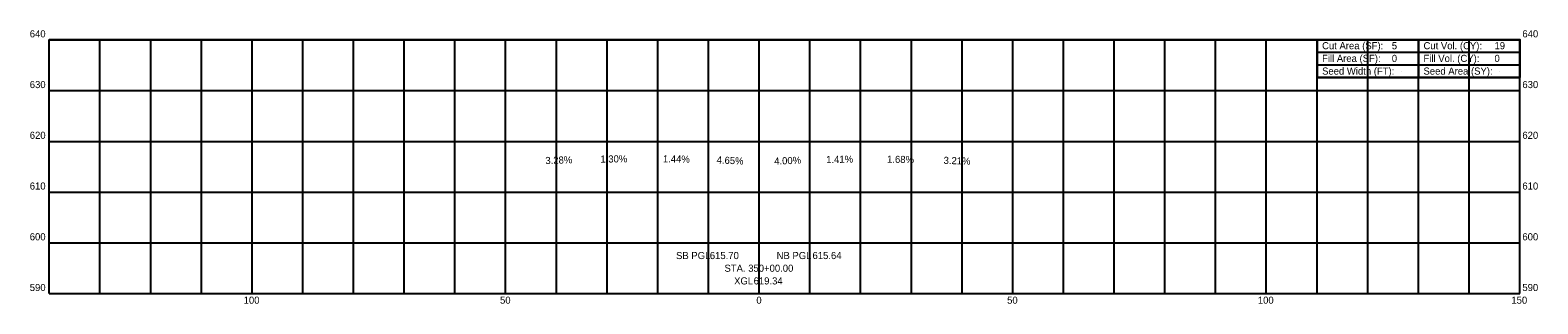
# Model space of a CAD drawing. Extents: x -144 to 154, y 588 to 642.
import ezdxf

# ---------------------------------------------------------------- set-up
doc = ezdxf.new("R2010")
doc.units = 0
for name, color, linetype in [('Default', 7, 'Continuous'), ('SH_Data', 7, 'Continuous'), ('SH_Major_Grid_Line', 7, 'Continuous'), ('SH_Masking', 7, 'Continuous'), ('SH_Text', 7, 'Continuous')]:
    doc.layers.add(name, color=color, linetype=linetype)

msp = doc.modelspace()

# ---------------------------------------------------------------- linework, layer by layer
at = {"layer": 'Default'}
msp.add_circle((150, 640.11), 0.000833, dxfattribs=at)
msp.add_circle((150, 640.11), 0.000833, dxfattribs=at)
msp.add_circle((150, 640.11), 0.000833, dxfattribs=at)
msp.add_circle((150, 640.11), 0.000833, dxfattribs=at)
msp.add_circle((150, 640.11), 0.000833, dxfattribs=at)
msp.add_circle((150, 640.11), 0.000833, dxfattribs=at)
msp.add_circle((150, 640.11), 0.000833, dxfattribs=at)
msp.add_circle((150, 640.11), 0.000833, dxfattribs=at)
msp.add_circle((150, 640.11), 0.000833, dxfattribs=at)
msp.add_circle((150, 640.11), 0.000833, dxfattribs=at)
msp.add_circle((150, 640.11), 0.000833, dxfattribs=at)
msp.add_circle((150, 640.11), 0.000833, dxfattribs=at)
at = {"layer": 'SH_Data'}
for p, q in [((110, 640.11), (150, 640.11)), ((110, 640.11), (110, 635.11)), ((130, 640.11), (130, 632.61)), ((150, 640.11), (150, 635.11)), ((110, 637.61), (150, 637.61)), ((110, 635.11), (150, 635.11)), ((126.6, 633.86), (126.6, 633.86)), ((145.89, 633.86), (145.89, 633.86))]:
    msp.add_line(p, q, dxfattribs=at)
msp.add_lwpolyline([(110, 635.11), (110, 632.61), (150, 632.61), (150, 635.11)], dxfattribs=at)
at = {"layer": 'SH_Major_Grid_Line'}
for p, q in [((-140, 640.11), (150, 640.11)), ((-140, 590), (-140, 640.11)), ((-140, 640), (150, 640)), ((-130, 590), (-130, 640.11)), ((-120, 590), (-120, 640.11)), ((-110, 590), (-110, 640.11)), ((-100, 590), (-100, 640.11)), ((-90, 590), (-90, 640.11)), ((-80, 590), (-80, 640.11)), ((-70, 590), (-70, 640.11)), ((-60, 590), (-60, 640.11)), ((-50, 590), (-50, 640.11)), ((-40, 590), (-40, 640.11)), ((-30, 590), (-30, 640.11)), ((-20, 590), (-20, 640.11)), ((-10, 590), (-10, 640.11)), ((0, 590), (0, 640.11)), ((10, 590), (10, 640.11)), ((20, 590), (20, 640.11)), ((30, 590), (30, 640.11)), ((40, 590), (40, 640.11)), ((50, 590), (50, 640.11)), ((60, 590), (60, 640.11)), ((70, 590), (70, 640.11)), ((80, 590), (80, 640.11)), ((90, 590), (90, 640.11)), ((100, 590), (100, 640.11)), ((110, 590), (110, 640.11)), ((120, 590), (120, 640.11)), ((130, 590), (130, 640.11)), ((140, 590), (140, 640.11)), ((150, 590), (150, 640.11)), ((-140, 630), (150, 630)), ((-140, 620), (150, 620)), ((-140, 610), (150, 610)), ((-140, 600), (150, 600)), ((-140, 590), (150, 590))]:
    msp.add_line(p, q, dxfattribs=at)
at = {"layer": 'SH_Masking'}
msp.add_lwpolyline([(110, 640.11), (150, 640.11), (150, 632.61), (110, 632.61)], close=True, dxfattribs=at)

# ---------------------------------------------------------------- texts
at = {"layer": 'SH_Text'}
for s, p in [('640', (-143.85, 640.5)), ('Cut Area (SF):', (111, 638.16)), ('5', (124.75, 638.16)), ('Cut Vol. (CY):', (131, 638.16)), ('19', (145, 638.16)), ('640', (150.5, 640.5)), ('Fill Area (SF):', (111, 635.66)), ('0', (124.75, 635.66)), ('Fill Vol. (CY):', (131, 635.66)), ('0', (145, 635.66)), ('Seed Width (FT):', (111, 633.16)), ('Seed Area (SY):', (131, 633.16)), ('630', (-143.85, 630.5)), ('630', (150.5, 630.5)), ('620', (-143.85, 620.5)), ('620', (150.5, 620.5)), ('610', (-143.85, 610.5)), ('610', (150.5, 610.5)), ('600', (-143.85, 600.5)), ('600', (150.5, 600.5)), ('SB PGL ', (-16.4, 596.8)), ('615.70', (-9.74, 596.8)), ('NB PGL ', (3.43, 596.8)), ('615.64', (10.51, 596.8)), ('STA. 350+00.00', (-6.85, 594.3)), ('590', (-143.85, 590.5)), ('XGL ', (-4.95, 591.8)), ('619.34', (-1.1, 591.8)), ('590', (150.5, 590.5)), ('100', (-101.67, 588)), ('50', (-51.11, 588)), ('0', (-0.56, 588)), ('50', (48.89, 588)), ('100', (98.33, 588)), ('150', (148.33, 588))]:
    msp.add_text(s, height=1.4, dxfattribs=at).set_placement(p)
for s, rotation, p in [('3.28%', 1.8806, (-42.15, 615.52)), ('1.30%', 0.7445, (-31.32, 615.81)), ('1.44%', 359.1764, (-19, 615.87)), ('4.65%', 357.3384, (-8.42, 615.67)), ('4.00%', 2.2906, (2.98, 615.4)), ('1.41%', 0.808, (13.21, 615.73)), ('1.68%', 359.0362, (25.21, 615.79)), ('3.21%', 358.1595, (36.34, 615.57))]:
    msp.add_text(s, height=1.4, rotation=rotation, dxfattribs=at).set_placement(p)

doc.saveas('drawing.dxf')
